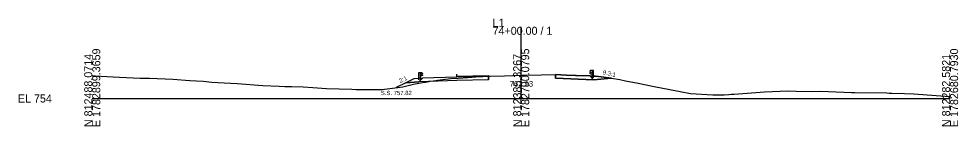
# Model space of a CAD drawing. Extents: x 5574 to 10203, y -10 to 9546.
# Drawn here: x 8574.3 to 8902.8, y 1990.3 to 2027.9 of the extents above; entities that cross this region are included whole.
import ezdxf

# ---------------------------------------------------------------- set-up
doc = ezdxf.new("R2010")
doc.units = 0
for name, color, linetype in [('Exist Cross Section Cell', 7, 'Continuous'), ('Exist XS Center Line Elevation Label', 7, 'Continuous'), ('Exist XS Ground Line', 7, 'Continuous'), ('Prop XS Ditch Slope Text', 7, 'Continuous'), ('Prop XS Dump Level', 7, 'Continuous'), ('Prop XS Earthwork Shape', 7, 'Continuous'), ('Prop XS EOT Tick Mark', 7, 'Continuous'), ('Prop XS Finish Grade', 7, 'Continuous'), ('Prop XS Finish Grade Earthwork', 7, 'Continuous'), ('Prop XS Finish Grade Paved Shoulder', 7, 'Continuous'), ('Prop XS Finish Grade Pavement', 7, 'Continuous'), ('Prop XS Guardrail', 7, 'Continuous'), ('Prop XS Pvmt Edge Slope', 7, 'Continuous'), ('Prop XS Side Slope Text', 7, 'Continuous'), ('Prop XS SS Elevation Text', 7, 'Continuous'), ('Prop XS Subgrade Earthwork', 7, 'Continuous'), ('Scratch_Level_3', 7, 'Continuous'), ('Scratch_Level_6', 7, 'Continuous')]:
    doc.layers.add(name, color=color, linetype=linetype)

msp = doc.modelspace()

# ---------------------------------------------------------------- linework, layer by layer
at = {"layer": 'Exist Cross Section Cell'}
for p, q in [((8750, 2000), (8750, 2025.08)), ((8600, 2000), (8750, 2000)), ((8750, 2000), (8900, 2000))]:
    msp.add_line(p, q, dxfattribs=at)
at = {"layer": 'Exist XS Ground Line'}
for p, q in [((8600, 2007.95), (8601.18, 2007.9)), ((8601.18, 2007.9), (8602.96, 2007.76)), ((8602.96, 2007.76), (8609.48, 2007.41)), ((8609.48, 2007.41), (8616.78, 2007.15)), ((8731.3, 2007.31), (8734.17, 2007.57)), ((8734.17, 2007.57), (8736.54, 2007.7)), ((8736.54, 2007.7), (8738.59, 2007.81)), ((8738.59, 2007.81), (8744.13, 2007.97)), ((8744.13, 2007.97), (8750, 2008.13)), ((8750, 2008.13), (8750.8, 2008.15)), ((8750.8, 2008.15), (8756.97, 2008.26)), ((8756.97, 2008.26), (8762.01, 2008.36)), ((8762.01, 2008.36), (8763.86, 2008.28)), ((8763.86, 2008.28), (8765.87, 2008.18)), ((8765.87, 2008.18), (8768.97, 2008.07)), ((8768.97, 2008.07), (8776.03, 2007.92)), ((8776.03, 2007.92), (8776.95, 2007.8)), ((8776.95, 2007.8), (8781.56, 2007.15)), ((8616.78, 2007.15), (8619.97, 2007.07)), ((8619.97, 2007.07), (8628.13, 2006.74)), ((8628.13, 2006.74), (8634.16, 2006.35)), ((8634.16, 2006.35), (8638.79, 2006.03)), ((8638.79, 2006.03), (8641.79, 2005.74)), ((8641.79, 2005.74), (8643.97, 2005.61)), ((8643.97, 2005.61), (8650.63, 2005.19)), ((8650.63, 2005.19), (8659.6, 2004.59)), ((8659.6, 2004.59), (8665.4, 2004.28)), ((8665.4, 2004.28), (8667.29, 2004.22)), ((8667.29, 2004.22), (8669.84, 2004.18)), ((8669.84, 2004.18), (8673.78, 2004.12)), ((8673.78, 2004.12), (8677.13, 2003.85)), ((8706.85, 2003.9), (8708.58, 2004.06)), ((8708.58, 2004.06), (8712.32, 2004.97)), ((8712.32, 2004.97), (8716.1, 2005.66)), ((8716.1, 2005.66), (8716.53, 2005.74)), ((8716.53, 2005.74), (8718.18, 2006.06)), ((8718.18, 2006.06), (8720.12, 2006.31)), ((8720.12, 2006.31), (8720.69, 2006.39)), ((8720.69, 2006.39), (8725.43, 2007.02)), ((8725.43, 2007.02), (8727.91, 2007.12)), ((8727.91, 2007.12), (8731.3, 2007.31)), ((8781.56, 2007.15), (8784.47, 2006.7)), ((8784.47, 2006.7), (8786.54, 2006.19)), ((8786.54, 2006.19), (8790.88, 2005.38)), ((8790.88, 2005.38), (8796.48, 2004.23)), ((8796.48, 2004.23), (8801.98, 2003.19)), ((8677.13, 2003.85), (8681.95, 2003.44)), ((8681.95, 2003.44), (8690.77, 2003.27)), ((8690.77, 2003.27), (8692.26, 2003.2)), ((8692.26, 2003.2), (8694.88, 2003.2)), ((8694.88, 2003.2), (8701.29, 2003.16)), ((8701.29, 2003.16), (8706.85, 2003.9)), ((8801.98, 2003.19), (8809.16, 2001.71)), ((8809.16, 2001.71), (8817, 2001.32)), ((8817, 2001.32), (8821.01, 2001.28)), ((8821.01, 2001.28), (8822.68, 2001.38)), ((8822.68, 2001.38), (8823.52, 2001.49)), ((8823.52, 2001.49), (8824.03, 2001.51)), ((8824.03, 2001.51), (8824.49, 2001.53)), ((8824.49, 2001.53), (8832.11, 2002.06)), ((8832.11, 2002.06), (8835.15, 2002.34)), ((8835.15, 2002.34), (8843.37, 2002.65)), ((8843.37, 2002.65), (8846.13, 2002.59)), ((8846.13, 2002.59), (8851.97, 2002.49)), ((8851.97, 2002.49), (8854.75, 2002.56)), ((8854.75, 2002.56), (8865.57, 2002.15)), ((8865.57, 2002.15), (8866.71, 2002.14)), ((8866.71, 2002.14), (8877.84, 2001.94)), ((8877.84, 2001.94), (8878.73, 2001.87)), ((8878.73, 2001.87), (8879.64, 2001.84)), ((8879.64, 2001.84), (8884, 2001.75)), ((8884, 2001.75), (8887.33, 2001.59)), ((8887.33, 2001.59), (8898.22, 2000.78)), ((8898.22, 2000.78), (8900, 2000.67))]:
    msp.add_line(p, q, dxfattribs=at)
at = {"layer": 'Prop XS Dump Level'}
msp.add_line((8738.64, 2007.9), (8727.49, 2007.68), dxfattribs=at)
at = {"layer": 'Prop XS Earthwork Shape'}
for points in [[(8738.59, 2007.81), (8738.61, 2007.81), (8738.61, 2006.56), (8727.52, 2006.25), (8717.76, 2005.98), (8718.18, 2006.06), (8720.12, 2006.31), (8720.69, 2006.39), (8725.43, 2007.02), (8727.91, 2007.12), (8731.3, 2007.31), (8734.17, 2007.57), (8736.54, 2007.7)], [(8776.03, 2007.92), (8776.95, 2007.8), (8781.56, 2007.15), (8775.3, 2006.58), (8762, 2007.11), (8762, 2008.36), (8763.86, 2008.28), (8765.87, 2008.18), (8768.97, 2008.07)], [(8716.53, 2005.74), (8717.76, 2005.98), (8714.2, 2005.88), (8709.67, 2005.51), (8706.29, 2003.82), (8706.85, 2003.9), (8708.58, 2004.06), (8712.32, 2004.97), (8716.1, 2005.66)]]:
    msp.add_lwpolyline(points, close=True, dxfattribs=at)
at = {"layer": 'Prop XS EOT Tick Mark'}
msp.add_line((8727.49, 2007.5), (8727.49, 2008.5), dxfattribs=at)
at = {"layer": 'Prop XS Finish Grade'}
for p, q in [((8774, 2007.88), (8777, 2007.64)), ((8777, 2007.64), (8781.56, 2007.15)), ((8712.49, 2006.92), (8709.67, 2005.51)), ((8715.49, 2007.16), (8712.49, 2006.92))]:
    msp.add_line(p, q, dxfattribs=at)
at = {"layer": 'Prop XS Finish Grade Earthwork'}
msp.add_line((8709.67, 2005.51), (8706.29, 2003.82), dxfattribs=at)
at = {"layer": 'Prop XS Finish Grade Paved Shoulder'}
msp.add_line((8727.49, 2007.5), (8715.49, 2007.16), dxfattribs=at)
at = {"layer": 'Prop XS Finish Grade Pavement'}
for p, q in [((8738.61, 2007.81), (8727.49, 2007.5)), ((8762, 2008.36), (8774, 2007.88))]:
    msp.add_line(p, q, dxfattribs=at)
at = {"layer": 'Prop XS Guardrail'}
for p, q in [((8714.17, 2009.04), (8714.67, 2009.04)), ((8714.17, 2006.54), (8714.17, 2009.04)), ((8714.67, 2009.04), (8715.17, 2009.04)), ((8714.67, 2009.04), (8714.67, 2006.54)), ((8715.17, 2007.9), (8714.67, 2007.9)), ((8715.17, 2009.04), (8715.46, 2008.84)), ((8715.46, 2008.72), (8715.17, 2008.52)), ((8715.17, 2008.52), (8715.17, 2008.42)), ((8715.17, 2008.42), (8715.46, 2008.22)), ((8715.46, 2008.1), (8715.17, 2007.9)), ((8715.46, 2008.84), (8715.49, 2008.78)), ((8715.49, 2008.78), (8715.46, 2008.72)), ((8715.46, 2008.22), (8715.49, 2008.16)), ((8715.49, 2008.16), (8715.46, 2008.1)), ((8774.03, 2009.55), (8774, 2009.49)), ((8774, 2009.49), (8774.03, 2009.43)), ((8774.03, 2008.94), (8774, 2008.88)), ((8774, 2008.88), (8774.03, 2008.82)), ((8774.32, 2009.75), (8774.03, 2009.55)), ((8774.03, 2009.43), (8774.32, 2009.23)), ((8774.32, 2009.14), (8774.03, 2008.94)), ((8774.03, 2008.82), (8774.32, 2008.62)), ((8774.82, 2009.75), (8774.32, 2009.75)), ((8774.32, 2009.23), (8774.32, 2009.14)), ((8774.32, 2008.62), (8774.82, 2008.62)), ((8775.32, 2009.75), (8774.82, 2009.75)), ((8774.82, 2009.75), (8774.82, 2007.25)), ((8775.32, 2007.25), (8775.32, 2009.75))]:
    msp.add_line(p, q, dxfattribs=at)
at = {"layer": 'Prop XS Pvmt Edge Slope'}
for p, q in [((8774, 2007.88), (8775.3, 2006.58)), ((8715.49, 2007.16), (8714.2, 2005.88))]:
    msp.add_line(p, q, dxfattribs=at)
at = {"layer": 'Prop XS Subgrade Earthwork'}
for p, q in [((8738.61, 2006.56), (8738.61, 2007.81)), ((8762, 2007.11), (8762, 2008.36)), ((8714.2, 2005.88), (8709.67, 2005.51)), ((8727.52, 2006.25), (8714.2, 2005.88)), ((8738.61, 2006.56), (8727.52, 2006.25)), ((8762, 2007.11), (8775.3, 2006.58)), ((8775.3, 2006.58), (8781.56, 2007.15))]:
    msp.add_line(p, q, dxfattribs=at)
at = {"layer": 'Scratch_Level_3'}
for p, q in [((8777, 2007.64), (8774, 2007.88)), ((8774, 2007.88), (8775.3, 2006.58)), ((8781.56, 2007.15), (8777, 2007.64)), ((8712.49, 2006.92), (8709.67, 2005.51)), ((8709.67, 2005.51), (8714.2, 2005.88)), ((8715.49, 2007.16), (8712.49, 2006.92)), ((8714.2, 2005.88), (8715.49, 2007.16)), ((8775.3, 2006.58), (8781.56, 2007.15))]:
    msp.add_line(p, q, dxfattribs=at)
at = {"layer": 'Scratch_Level_6'}
for points in [[(8717.76, 2005.98), (8718.18, 2006.06), (8720.12, 2006.31), (8720.69, 2006.39), (8725.43, 2007.02), (8727.91, 2007.12), (8731.3, 2007.31), (8734.17, 2007.57), (8736.54, 2007.7), (8738.59, 2007.81), (8738.61, 2007.81), (8738.61, 2006.56), (8727.52, 2006.25)], [(8775.3, 2006.58), (8781.56, 2007.15), (8777, 2007.64), (8774, 2007.88), (8769.29, 2008.07), (8768.97, 2008.07), (8765.87, 2008.18), (8763.86, 2008.28), (8762, 2008.36), (8762, 2007.11)]]:
    msp.add_lwpolyline(points, close=True, dxfattribs=at)

# ---------------------------------------------------------------- texts
at = {"layer": 'Exist Cross Section Cell'}
for s, p in [('L1', (8740, 2025.08)), ('74+00.00 / 1', (8740, 2022.28)), ('EL 754', (8574, 1998.6))]:
    msp.add_text(s, height=2.8, dxfattribs=at).set_placement(p)
for s, p in [('E 1782899.3659', (8602.8, 1990)), ('E 1782790.0795', (8752.8, 1990)), ('E 1782680.7930', (8902.8, 1990)), ('N 812488.0714', (8600, 1990)), ('N 812385.3267', (8750, 1990)), ('N 812282.5821', (8900, 1990))]:
    msp.add_text(s, height=2.8, rotation=90, dxfattribs=at).set_placement(p)
at = {"layer": 'Exist XS Center Line Elevation Label'}
msp.add_text('762.13', height=2, dxfattribs=at).set_placement((8745.99, 2004.13))
at = {"layer": 'Prop XS Ditch Slope Text'}
msp.add_text('9.3:1', height=1.5, rotation=347.8076, dxfattribs=at).set_placement((8778.42, 2008.48))
at = {"layer": 'Prop XS Dump Level'}
for s, height, p in [('Eop', 0.3, (8738.61, 2007.51)), ('Case4', 0.04, (8715.49, 2006.71))]:
    msp.add_text(s, height=height, dxfattribs=at).set_placement(p)
at = {"layer": 'Prop XS Side Slope Text'}
msp.add_text('2:1', height=1.5, rotation=26.5651, dxfattribs=at).set_placement((8707.75, 2005.37))
at = {"layer": 'Prop XS SS Elevation Text'}
msp.add_text('S.S. 757.82', height=1.5, dxfattribs=at).set_placement((8700.93, 2001.18))

doc.saveas('drawing.dxf')
